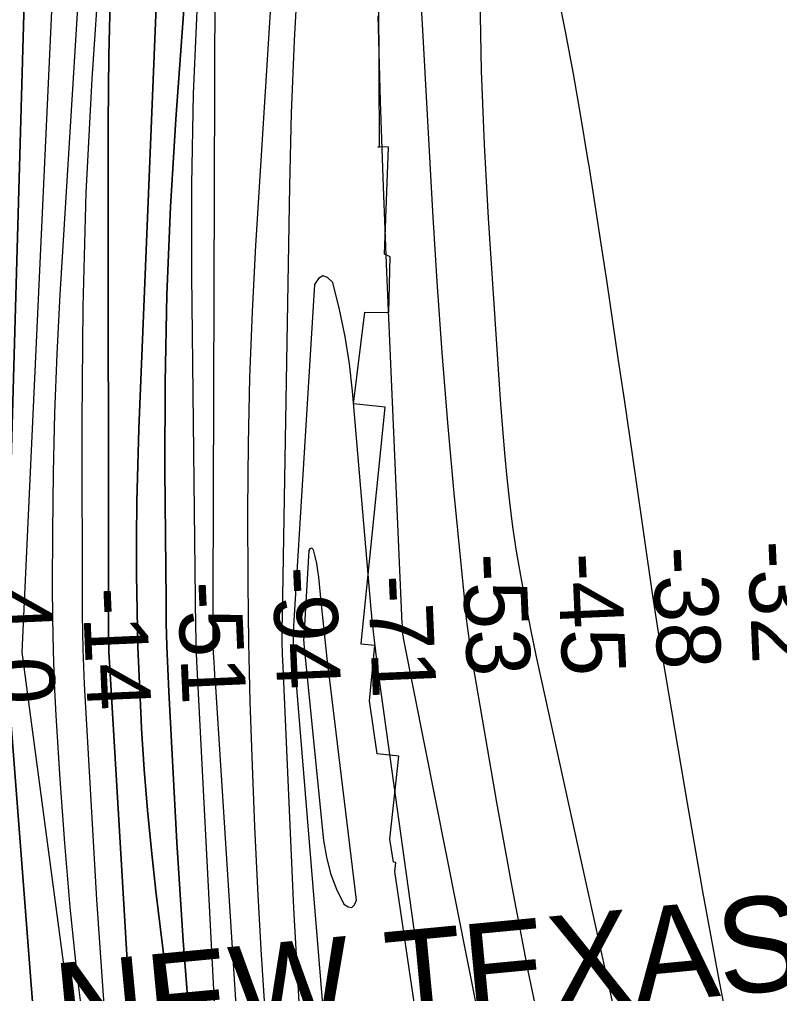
# Model space of a CAD drawing. Extents: x 3187622 to 3225504, y 800805 to 826213.
# Drawn here: x 3197117 to 3197916, y 821579 to 822602 of the extents above; entities that cross this region are included whole.
import ezdxf

# ---------------------------------------------------------------- set-up
doc = ezdxf.new("R2010")
doc.units = 0
for name, color, linetype in [('V-CHAN-NAID', 7, 'Continuous'), ('V-RIVR-RANG', 7, 'Continuous'), ('V-RRAP-RVMT', 7, 'Continuous'), ('V-TOPO-DPTH', 7, 'Continuous'), ('V-TOPO-MAJR', 7, 'Continuous'), ('V-TOPO-MINR', 7, 'Continuous'), ('V-TOPO-WATR', 7, 'Continuous')]:
    doc.layers.add(name, color=color, linetype=linetype)

msp = doc.modelspace()

# ---------------------------------------------------------------- linework, layer by layer
at = {"layer": 'V-RRAP-RVMT'}
for p, q in [((3197495.4, 822468.3), (3197493.1, 823063.9)), ((3197505, 822467.9), (3197493.8, 822468.3)), ((3197493.8, 822468.3), (3197495.4, 822468.3)), ((3197500.7, 822355.4), (3197505, 822467.9)), ((3197506.5, 822352.7), (3197500.7, 822355.4)), ((3197505.2, 822294.1), (3197506.5, 822352.7)), ((3197468, 822198.2), (3197480, 822294.6)), ((3197480, 822294.6), (3197505.2, 822294.1)), ((3197501.2, 822194.5), (3197468, 822198.2)), ((3197476, 821946.2), (3197501.2, 822194.5)), ((3197476.1, 821945.6), (3197476, 821946.2)), ((3197490.5, 821944.3), (3197476.1, 821945.6)), ((3197484.9, 821886), (3197490.5, 821944.3)), ((3197493.1, 821830.5), (3197484.9, 821886)), ((3197515.9, 821828.1), (3197493.1, 821830.5)), ((3197506.4, 821740.9), (3197515.9, 821828.1)), ((3197510, 821716.6), (3197506.4, 821740.9)), ((3197512.5, 821716.3), (3197510, 821716.6)), ((3197511.5, 821706.8), (3197512.5, 821716.3)), ((3197538, 821527.9), (3197511.5, 821706.8))]:
    msp.add_line(p, q, dxfattribs=at)
at = {"layer": 'V-TOPO-DPTH'}
for points in [[(3197194.3, 822876), (3197159.8, 822313.1), (3197156.5, 822250.8), (3197154, 822188.4), (3197152.5, 822126), (3197151.8, 822063.6), (3197151.6, 822006.8), (3197151.9, 821972.8), (3197152.5, 821938.7), (3197153.8, 821904.7), (3197155.6, 821870.6), (3197159.6, 821803.8), (3197164.4, 821736.4), (3197170.1, 821669.2), (3197177.3, 821602), (3197185.4, 821535), (3197270, 820896.2), (3197272.8, 820877.8), (3197276.3, 820859.5), (3197280.6, 820841.4), (3197285.4, 820823.4), (3197357.1, 820581.1)], [(3197194.3, 822876), (3197159.8, 822313.1), (3197156.5, 822250.8), (3197154, 822188.4), (3197152.5, 822126), (3197151.8, 822063.6), (3197151.6, 822006.8), (3197151.9, 821972.8), (3197152.5, 821938.7), (3197153.8, 821904.7), (3197155.6, 821870.6), (3197159.6, 821803.8), (3197164.4, 821736.4), (3197170.1, 821669.2), (3197177.3, 821602), (3197185.4, 821535), (3197270, 820896.2), (3197272.8, 820877.8), (3197276.3, 820859.5), (3197280.6, 820841.4), (3197285.4, 820823.4), (3197357.1, 820581.1)], [(3197593.8, 820054.6), (3197385.4, 820843), (3197381.4, 820859.5), (3197377.8, 820876.2), (3197374.8, 820893), (3197372.4, 820909.8), (3197319.6, 821325.4), (3197307.7, 821428.1), (3197297.3, 821530.9), (3197289.2, 821633.9), (3197282.6, 821737.1), (3197274.1, 821895.8), (3197273, 821919.7), (3197272.1, 821943.7), (3197271.5, 821967.6), (3197271.2, 821991.5), (3197269.9, 822128.3), (3197270.2, 822220.6), (3197272, 822312.9), (3197276, 822405.1), (3197281.6, 822497.2), (3197308.8, 822872.4)], [(3197308.8, 822872.4), (3197281.6, 822497.2), (3197276, 822405.1), (3197272, 822312.9), (3197270.2, 822220.6), (3197269.9, 822128.3), (3197271.2, 821991.5), (3197271.5, 821967.6), (3197272.1, 821943.7), (3197273, 821919.7), (3197274.1, 821895.8), (3197282.6, 821737.1), (3197289.2, 821633.9), (3197297.3, 821530.9), (3197307.7, 821428.1), (3197319.6, 821325.4), (3197372.4, 820909.8), (3197374.8, 820893), (3197377.8, 820876.2), (3197381.4, 820859.5), (3197385.4, 820843), (3197593.8, 820054.6)], [(3197453.4, 820481.7), (3197371.8, 820823.8), (3197366.3, 820848.7), (3197361.4, 820873.6), (3197357.3, 820898.8), (3197353.8, 820924), (3197260.6, 821686.3), (3197255.8, 821728.8), (3197251.6, 821771.4), (3197248.3, 821814.1), (3197245.5, 821856.8), (3197245, 821866), (3197243.2, 821904.2), (3197241.7, 821942.4), (3197240.8, 821980.6), (3197240.2, 822018.9), (3197240.3, 822057.1), (3197240.6, 822095.4), (3197241.5, 822133.6), (3197242.8, 822171.8), (3197271, 822862.8)], [(3197271, 822862.8), (3197242.8, 822171.8), (3197241.5, 822133.6), (3197240.6, 822095.4), (3197240.3, 822057.1), (3197240.2, 822018.9), (3197240.8, 821980.6), (3197241.7, 821942.4), (3197243.2, 821904.2), (3197245, 821866), (3197245.5, 821856.8), (3197248.3, 821814.1), (3197251.6, 821771.4), (3197255.8, 821728.8), (3197260.6, 821686.3), (3197353.8, 820924), (3197357.3, 820898.8), (3197361.4, 820873.6), (3197366.3, 820848.7), (3197371.8, 820823.8), (3197453.4, 820481.7)], [(3197279.5, 820630.3), (3197266.2, 820664.5), (3197261, 820677.8), (3197250.5, 820705.4), (3197240.6, 820733.3), (3197231.3, 820761.4), (3197222.6, 820789.6), (3197207.9, 820839.2), (3197207, 820842.8), (3197206.1, 820846.5), (3197205.3, 820850.1), (3197204.7, 820853.8), (3197185.9, 820979.4), (3197176.7, 821046), (3197168.4, 821112.7), (3197161.6, 821179.6), (3197155.7, 821246.6), (3197104.1, 821919.9), (3197103.6, 821928.3), (3197103.3, 821936.7), (3197103.2, 821945.1), (3197103.3, 821953.5), (3197124.1, 822682.1)], [(3197124.1, 822682.1), (3197103.3, 821953.5), (3197103.2, 821945.1), (3197103.3, 821936.7), (3197103.6, 821928.3), (3197104.1, 821919.9), (3197155.7, 821246.6), (3197161.6, 821179.6), (3197168.4, 821112.7), (3197176.7, 821046), (3197185.9, 820979.4), (3197204.7, 820853.8), (3197205.3, 820850.1), (3197206.1, 820846.5), (3197207, 820842.8), (3197207.9, 820839.2), (3197222.6, 820789.6), (3197231.3, 820761.4), (3197240.6, 820733.3), (3197250.5, 820705.4), (3197261, 820677.8), (3197266.2, 820664.5), (3197279.5, 820630.3)], [(3197371.2, 820609), (3197352, 820672.4), (3197333.4, 820735.9), (3197300.9, 820848.8), (3197299, 820856), (3197297.4, 820863.3), (3197296, 820870.6), (3197294.9, 820878), (3197276.6, 821018.3), (3197267.4, 821096), (3197259.2, 821173.8), (3197252.6, 821251.7), (3197247.2, 821329.7), (3197211.5, 821932.5), (3197211.2, 821936.8), (3197211.1, 821941.1), (3197211, 821945.4), (3197210.9, 821949.7), (3197210.3, 822492.9), (3197211, 822564.2), (3197212.9, 822635.4)], [(3197212.9, 822635.4), (3197211, 822564.2), (3197210.3, 822492.9), (3197210.9, 821949.7), (3197211, 821945.4), (3197211.1, 821941.1), (3197211.2, 821936.8), (3197211.5, 821932.5), (3197247.2, 821329.7), (3197252.6, 821251.7), (3197259.2, 821173.8), (3197267.4, 821096), (3197276.6, 821018.3), (3197294.9, 820878), (3197296, 820870.6), (3197297.4, 820863.3), (3197299, 820856), (3197300.9, 820848.8), (3197333.4, 820735.9), (3197352, 820672.4), (3197371.2, 820609)]]:
    msp.add_lwpolyline(points, dxfattribs=at)
at = {"layer": 'V-TOPO-MAJR'}
for points in [[(3197870.4, 821500.2), (3197852.2, 821592.8), (3197835.1, 821685.7), (3197818.8, 821778.7), (3197792.5, 821933.5), (3197789.9, 821949.3), (3197787.4, 821965), (3197785, 821980.7), (3197782.6, 821996.5), (3197764.5, 822120.6), (3197758.6, 822161.6), (3197752.6, 822202.6), (3197746.6, 822243.6), (3197740.6, 822284.5), (3197734.6, 822325.5), (3197728.4, 822366.4), (3197722, 822407.3), (3197715.5, 822448.2), (3197714.3, 822455.7), (3197706.8, 822500.3), (3197699.1, 822544.8), (3197690.8, 822589.2), (3197682.2, 822633.5)], [(3197303.9, 822619.2), (3197299.8, 822524), (3197298.1, 822428.6), (3197298, 822333.3), (3197302.2, 821962), (3197302.4, 821953.4), (3197302.6, 821944.9), (3197302.9, 821936.4), (3197303.3, 821927.9), (3197324.8, 821508.1), (3197331.3, 821402.7), (3197339.5, 821297.4), (3197350, 821192.4), (3197362, 821087.4), (3197385.7, 820899.8), (3197387.3, 820888.9), (3197389.2, 820877.9), (3197391.5, 820867.1), (3197394.1, 820856.4), (3197486.5, 820505.1)], [(3197415.7, 821949.6), (3197415.8, 821947.7), (3197415.9, 821945.7), (3197436.7, 821739.2), (3197439.6, 821721.7), (3197443.9, 821704.7), (3197450.2, 821688.3), (3197457.9, 821672.4), (3197462.5, 821669.7), (3197466.3, 821669.1), (3197469.1, 821671.9), (3197471.2, 821676.8), (3197442.9, 821910.6), (3197440.5, 821930.6), (3197438.3, 821950.5), (3197436.2, 821970.5), (3197434.1, 821990.5), (3197431.7, 822015.9), (3197430.7, 822023.2), (3197429.6, 822030.4), (3197428, 822037.6), (3197426.2, 822044.7), (3197424.8, 822046), (3197423.5, 822046.5), (3197422.4, 822045.7), (3197421.3, 822044.2), (3197415.8, 821953.5), (3197415.7, 821949.6)]]:
    msp.add_lwpolyline(points, dxfattribs=at)
at = {"layer": 'V-TOPO-MINR'}
for points in [[(3197164.2, 822898.6), (3197119.6, 821937.4), (3197257.5, 820905.2), (3197261.3, 820881.3), (3197265.8, 820857.6), (3197271.4, 820834.1), (3197277.8, 820810.8), (3197401.7, 820396.9)], [(3197194.3, 822876), (3197159.8, 822313.1), (3197156.5, 822250.8), (3197154, 822188.4), (3197152.5, 822126), (3197151.8, 822063.6), (3197151.6, 822006.8), (3197151.9, 821972.8), (3197152.5, 821938.7), (3197153.8, 821904.7), (3197155.6, 821870.6), (3197159.6, 821803.8), (3197164.4, 821736.4), (3197170.1, 821669.2), (3197177.3, 821602), (3197185.4, 821535), (3197270, 820896.2), (3197272.8, 820877.8), (3197276.3, 820859.5), (3197280.6, 820841.4), (3197285.4, 820823.4), (3197357.1, 820581.1)], [(3197308.8, 822872.4), (3197281.6, 822497.2), (3197276, 822405.1), (3197272, 822312.9), (3197270.2, 822220.6), (3197269.9, 822128.3), (3197271.2, 821991.5), (3197271.5, 821967.6), (3197272.1, 821943.7), (3197273, 821919.7), (3197274.1, 821895.8), (3197282.6, 821737.1), (3197289.2, 821633.9), (3197297.3, 821530.9), (3197307.7, 821428.1), (3197319.6, 821325.4), (3197372.4, 820909.8), (3197374.8, 820893), (3197377.8, 820876.2), (3197381.4, 820859.5), (3197385.4, 820843), (3197593.8, 820054.6)], [(3197271, 822862.8), (3197242.8, 822171.8), (3197241.5, 822133.6), (3197240.6, 822095.4), (3197240.3, 822057.1), (3197240.2, 822018.9), (3197240.8, 821980.6), (3197241.7, 821942.4), (3197243.2, 821904.2), (3197245, 821866), (3197245.5, 821856.8), (3197248.3, 821814.1), (3197251.6, 821771.4), (3197255.8, 821728.8), (3197260.6, 821686.3), (3197353.8, 820924), (3197357.3, 820898.8), (3197361.4, 820873.6), (3197366.3, 820848.7), (3197371.8, 820823.8), (3197453.4, 820481.7)], [(3197395.4, 822844.8), (3197365.3, 822364.5), (3197361.6, 822295), (3197358.8, 822225.5), (3197357.4, 822156), (3197356.9, 822086.4), (3197357.1, 822009.4), (3197357.3, 821978.3), (3197357.7, 821947.2), (3197358.4, 821916.1), (3197359.3, 821885), (3197361.6, 821818.1), (3197364.1, 821753.6), (3197367.1, 821689.1)], [(3197201.3, 822659.2), (3197193.2, 822539.5), (3197187.1, 822419.8), (3197183.9, 822299.9), (3197182.7, 822180), (3197183.2, 821976.3), (3197183.4, 821958.2), (3197183.7, 821940), (3197184.4, 821921.9), (3197185.3, 821903.7), (3197198.2, 821677.5), (3197207.2, 821546.4), (3197218, 821415.4), (3197231.7, 821284.8), (3197247.4, 821154.3), (3197282.4, 820887.1), (3197284.4, 820874.2), (3197286.8, 820861.4), (3197289.8, 820848.7), (3197293.2, 820836.1), (3197346.2, 820654.2), (3197377.2, 820550.9)], [(3197410, 822656.3), (3197405.7, 822579.9), (3197402.8, 822503.5), (3197400.8, 822427.1), (3197393.1, 821975.4), (3197393, 821962), (3197393, 821948.6), (3197393.3, 821935.3), (3197393.8, 821921.9), (3197405, 821668.2), (3197412.3, 821538.7), (3197421.4, 821409.4)], [(3197212.9, 822635.4), (3197211, 822564.2), (3197210.3, 822492.9), (3197210.9, 821949.7), (3197211, 821945.4), (3197211.1, 821941.1), (3197211.2, 821936.8), (3197211.5, 821932.5), (3197247.2, 821329.7), (3197252.6, 821251.7), (3197259.2, 821173.8), (3197267.4, 821096), (3197276.6, 821018.3), (3197294.9, 820878), (3197296, 820870.6), (3197297.4, 820863.3), (3197299, 820856), (3197300.9, 820848.8), (3197333.4, 820735.9), (3197352, 820672.4), (3197371.2, 820609)], [(3197322.4, 822641.8), (3197320.4, 821992.5), (3197320.4, 821985.7), (3197320.4, 821978.9), (3197320.4, 821972.2), (3197320.3, 821965.4), (3197320.3, 821954.9), (3197320.3, 821953.4), (3197320.3, 821950.3), (3197320.3, 821945.7)], [(3197670, 821514.1), (3197651.7, 821602.3), (3197634.7, 821690.7), (3197618.8, 821779.3), (3197593.5, 821926.2), (3197591.1, 821941.5), (3197588.8, 821956.8), (3197586.9, 821972.2), (3197585.3, 821987.6), (3197574, 822104.4), (3197567.3, 822178.3), (3197561.3, 822252.2), (3197556.1, 822326.2), (3197551.5, 822400.2), (3197540.6, 822596.9), (3197538.9, 822627.6)], [(3197760.8, 821477.9), (3197733.8, 821598.2), (3197707.1, 821718.6), (3197666.2, 821905.2), (3197660.4, 821932.3), (3197654.8, 821959.6), (3197649.5, 821986.8), (3197644.4, 822014.1), (3197643.7, 822017.9), (3197639.4, 822043.4), (3197635.5, 822069), (3197632.3, 822094.7), (3197629.5, 822120.4), (3197627.1, 822146.2), (3197624.9, 822172), (3197622.9, 822197.8), (3197621.1, 822223.7), (3197610, 822393.3), (3197605.8, 822470.7), (3197602.7, 822548), (3197601.2, 822625.5)], [(3197895.1, 820450.9), (3197754.1, 820868.4), (3197742.5, 820904), (3197731.4, 820939.9), (3197721.2, 820976), (3197711.5, 821012.2), (3197711.5, 821012.3), (3197702.5, 821048.8), (3197693.9, 821085.4), (3197685.8, 821122.1), (3197678.2, 821158.9), (3197520.8, 821951.9), (3197520.6, 821952.9), (3197520.1, 821956), (3197519.9, 821958), (3197519.7, 821961.1), (3197519.6, 821964.3), (3197519.5, 821965.9), (3197519.4, 821967.5), (3197503.2, 822336.5), (3197499.6, 822426.3), (3197496.4, 822516.1), (3197494, 822605.9)], [(3197551.1, 821517.3), (3197533.3, 821635.9), (3197493.4, 821922.9), (3197491.5, 821937.8), (3197489.7, 821952.7), (3197488.2, 821967.6), (3197486.8, 821982.5), (3197467.2, 822211.4), (3197463.9, 822240.3), (3197459.5, 822269), (3197453.5, 822297.4), (3197446.4, 822325.6), (3197440.9, 822330.8), (3197435.8, 822332.7), (3197431.2, 822329.7), (3197427, 822323.5), (3197405, 821964.4), (3197404.7, 821956.8), (3197404.6, 821949.1)], [(3197404.6, 821949.1), (3197404.9, 821941.5), (3197405.3, 821933.8), (3197467.4, 821179), (3197471.6, 821131.9), (3197476.3, 821084.9), (3197481.6, 821038), (3197487.4, 820991.1), (3197498.3, 820906.8), (3197499, 820902.1), (3197499.8, 820897.5), (3197500.7, 820892.9), (3197501.7, 820888.3), (3197666.6, 820193.9)], [(3197320.3, 821945.7), (3197320.5, 821941.3), (3197320.6, 821938.4), (3197320.7, 821937), (3197321.3, 821926.9), (3197321.8, 821920.4), (3197322.2, 821913.9), (3197322.6, 821907.3), (3197323, 821900.8), (3197370.2, 821166.2), (3197373.7, 821118.3), (3197377.8, 821070.4), (3197382.8, 821022.7), (3197388.3, 820975), (3197399, 820889.8), (3197399.8, 820884.7), (3197400.6, 820879.7), (3197401.7, 820874.7), (3197402.9, 820869.8), (3197439.5, 820729.6), (3197459.8, 820654.7), (3197480.8, 820580)], [(3197367.1, 821689.1), (3197370.8, 821624.7), (3197375, 821560.2), (3197418.6, 820945.7), (3197421.4, 820914.7), (3197425.1, 820883.8), (3197430, 820853.1), (3197435.8, 820822.5), (3197442.6, 820792), (3197449.9, 820761.8), (3197458, 820731.7), (3197466.6, 820701.7), (3197742.1, 819787.9)]]:
    msp.add_lwpolyline(points, dxfattribs=at)
at = {"layer": 'V-TOPO-WATR'}
msp.add_lwpolyline([(3197124.1, 822682.1), (3197103.3, 821953.5), (3197103.2, 821945.1), (3197103.3, 821936.7), (3197103.6, 821928.3), (3197104.1, 821919.9), (3197155.7, 821246.6), (3197161.6, 821179.6), (3197168.4, 821112.7), (3197176.7, 821046), (3197185.9, 820979.4), (3197204.7, 820853.8), (3197205.3, 820850.1), (3197206.1, 820846.5), (3197207, 820842.8), (3197207.9, 820839.2), (3197222.6, 820789.6), (3197231.3, 820761.4), (3197240.6, 820733.3), (3197250.5, 820705.4), (3197261, 820677.8), (3197266.2, 820664.5), (3197279.5, 820630.3)], dxfattribs=at)

# ---------------------------------------------------------------- texts
at = {"layer": 'V-CHAN-NAID'}
msp.add_text('NEW TEXAS (279.7)', height=100, rotation=5.4403, dxfattribs=at).set_placement((3197159.2, 821510))
at = {"layer": 'V-RIVR-RANG'}
for s, p in [('-32', (3197881.8, 822053.5)), ('-38', (3197782, 822047.3)), ('-53', (3197582.1, 822040.1)), ('-45', (3197682.2, 822040.5)), ('-94', (3197382.5, 822026.3)), ('-51', (3197283.1, 822010.6)), ('-71', (3197483, 822017.2)), ('4.0', (3197083.1, 822005.5)), ('-14', (3197183.3, 822004.3))]:
    msp.add_text(s, height=67, rotation=272.4991, dxfattribs=at).set_placement(p)

doc.saveas('drawing.dxf')
